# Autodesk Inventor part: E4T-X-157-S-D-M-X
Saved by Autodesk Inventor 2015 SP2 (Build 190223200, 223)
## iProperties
Created: 2016-05
Part Number: E4T-X-157-S-D-M-X
Material: Allgemein
Document SubType Name: Modeling
Designer: ryll
Density: 1 g/cm^3
Appearance: Vorgabe
Author: ryll
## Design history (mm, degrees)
node "E4T-X-157-S-D-M-X1"
node "E4T-X-157-S-D-M-X"
node "Basis1"
